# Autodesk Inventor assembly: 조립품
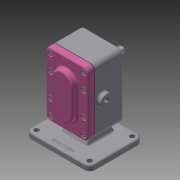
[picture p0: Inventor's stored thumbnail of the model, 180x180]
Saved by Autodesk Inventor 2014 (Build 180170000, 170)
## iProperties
Created: 2020-04
Part Number: 조립품
Document SubType Name: Assembly
Designer: kh
Author: kh
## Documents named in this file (11)
- C:\Users\kh\Desktop\700407V1012\조립품.iam
- C:\Users\kh\Desktop\700407V1012\본체.ipt
- C:\Users\kh\Desktop\700407V1012\개스킷.ipt
- C:\Users\kh\Desktop\700407V1012\메인축.ipt
- C:\Users\kh\Desktop\700407V1012\베어링부시.ipt
- C:\Users\kh\Desktop\700407V1012\볼트 M5.ipt
- C:\Users\kh\Desktop\700407V1012\서브축.ipt
- C:\Users\kh\Desktop\700407V1012\스퍼기어.ipt
- C:\Users\kh\Desktop\700407V1012\오일 실 16 28 7.ipt
- C:\Users\kh\Desktop\700407V1012\커버.ipt
- C:\Users\kh\Desktop\700407V1012\키 6 x 6 x 18.ipt
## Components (1 placed, 1 different names)
1. 개스킷:1 — 플러쉬:1, 플러쉬:2
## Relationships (2: Flush 2)
- 플러쉬:1 [Flush]: 개스킷:1
- 플러쉬:2 [Flush]: 개스킷:1
